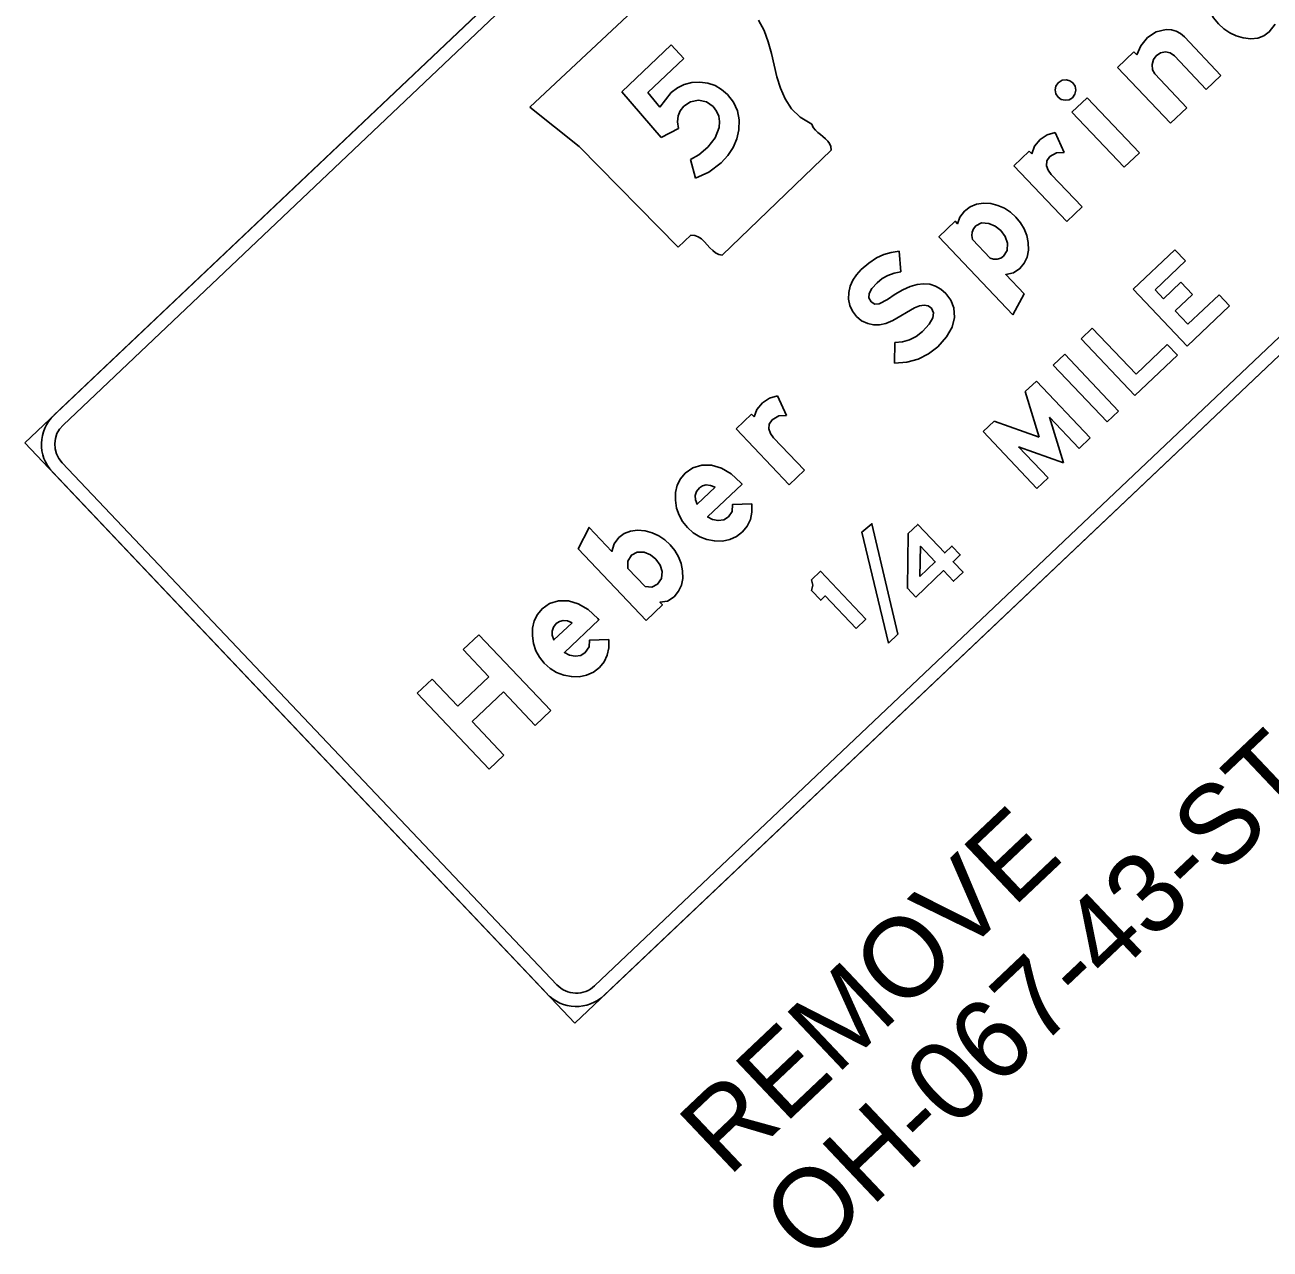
# Model space of a CAD drawing. Extents: x 1289840 to 1295361, y 220865 to 226414.
# Drawn here: x 1291418.9 to 1291512.4, y 222085.2 to 222177.1 of the extents above; entities that cross this region are included whole.
import ezdxf

# ---------------------------------------------------------------- set-up
doc = ezdxf.new("R2010")
doc.units = 0
doc.layers.add('P_TC_Signs_Permanent', color=7, linetype='Continuous')
doc.layers.add('R_OVHD_Sign', color=7, linetype='Continuous')

msp = doc.modelspace()

# ---------------------------------------------------------------- linework, layer by layer
at = {"layer": 'R_OVHD_Sign'}
for p, q in [((1291497.277, 222220.036), (1291418.89, 222145.744)), ((1291421.067, 222147.808), (1291495.1, 222217.973)), ((1291495.788, 222217.247), (1291421.755, 222147.082)), ((1291456.789, 222170.942), (1291468.823, 222182.203)), ((1291473.961, 222177.469), (1291474.386, 222176.683)), ((1291460.163, 222102.195), (1291538.551, 222176.488)), ((1291474.386, 222176.683), (1291474.695, 222175.844)), ((1291503.819, 222176.59), (1291503.173, 222176.157)), ((1291504.56, 222176.759), (1291503.819, 222176.59)), ((1291504.954, 222176.738), (1291504.56, 222176.759)), ((1291505.317, 222176.641), (1291504.954, 222176.738)), ((1291505.645, 222176.463), (1291505.317, 222176.641)), ((1291467.416, 222175.609), (1291463.706, 222172.093)), ((1291468.368, 222174.604), (1291467.416, 222175.609)), ((1291474.695, 222175.844), (1291474.929, 222174.976)), ((1291502.668, 222175.546), (1291502.358, 222174.861)), ((1291503.173, 222176.157), (1291502.668, 222175.546)), ((1291505.943, 222176.208), (1291505.645, 222176.463)), ((1291508.679, 222173.321), (1291505.943, 222176.208)), ((1291461.653, 222104.985), (1291535.685, 222175.15)), ((1291465.654, 222172.031), (1291468.368, 222174.604)), ((1291474.929, 222174.976), (1291475.133, 222174.084)), ((1291502.144, 222175.086), (1291500.917, 222173.922)), ((1291502.358, 222174.861), (1291502.144, 222175.086)), ((1291503.609, 222174.506), (1291503.817, 222174.796)), ((1291503.817, 222174.796), (1291504.149, 222175.022)), ((1291504.149, 222175.022), (1291504.509, 222175.101)), ((1291504.509, 222175.101), (1291504.864, 222175.023)), ((1291504.864, 222175.023), (1291505.185, 222174.785)), ((1291505.185, 222174.785), (1291507.569, 222172.269)), ((1291536.373, 222174.424), (1291462.341, 222104.259)), ((1291475.133, 222174.084), (1291475.343, 222173.209)), ((1291500.917, 222173.922), (1291504.89, 222169.73)), ((1291503.512, 222174.137), (1291503.609, 222174.506)), ((1291503.537, 222173.74), (1291503.512, 222174.137)), ((1291503.712, 222173.432), (1291503.537, 222173.74)), ((1291468.947, 222172.786), (1291468.389, 222172.645)), ((1291469.55, 222172.818), (1291468.947, 222172.786)), ((1291470.151, 222172.738), (1291469.55, 222172.818)), ((1291470.699, 222172.561), (1291470.151, 222172.738)), ((1291475.343, 222173.209), (1291475.602, 222172.358)), ((1291496.467, 222172.769), (1291496.286, 222172.517)), ((1291496.758, 222172.954), (1291496.467, 222172.769)), ((1291497.08, 222172.995), (1291496.758, 222172.954)), ((1291497.339, 222172.912), (1291497.08, 222172.995)), ((1291497.566, 222172.757), (1291497.339, 222172.912)), ((1291497.723, 222172.508), (1291497.566, 222172.757)), ((1291506.118, 222170.893), (1291503.712, 222173.432)), ((1291507.569, 222172.269), (1291508.679, 222173.321)), ((1291463.706, 222172.093), (1291466.657, 222168.656)), ((1291466.558, 222170.935), (1291465.654, 222172.031)), ((1291467.412, 222172.028), (1291466.558, 222170.935)), ((1291467.877, 222172.39), (1291467.412, 222172.028)), ((1291468.389, 222172.645), (1291467.877, 222172.39)), ((1291471.195, 222172.274), (1291470.699, 222172.561)), ((1291471.637, 222171.889), (1291471.195, 222172.274)), ((1291472.087, 222171.306), (1291471.637, 222171.889)), ((1291475.602, 222172.358), (1291475.957, 222171.558)), ((1291496.286, 222172.517), (1291496.228, 222172.234)), ((1291496.228, 222172.234), (1291496.286, 222171.948)), ((1291496.286, 222171.948), (1291496.452, 222171.701)), ((1291497.525, 222171.651), (1291497.71, 222171.906)), ((1291497.71, 222171.906), (1291497.774, 222172.209)), ((1291497.774, 222172.209), (1291497.723, 222172.508)), ((1291460.498, 222167.999), (1291456.789, 222170.942)), ((1291468.08, 222170.671), (1291468.345, 222171.005)), ((1291468.345, 222171.005), (1291468.862, 222171.342)), ((1291468.862, 222171.342), (1291469.464, 222171.454)), ((1291469.464, 222171.454), (1291470.056, 222171.333)), ((1291470.056, 222171.333), (1291470.548, 222170.983)), ((1291470.548, 222170.983), (1291470.814, 222170.632)), ((1291472.378, 222170.672), (1291472.087, 222171.306)), ((1291475.957, 222171.558), (1291476.444, 222170.826)), ((1291496.452, 222171.701), (1291496.692, 222171.524)), ((1291496.692, 222171.524), (1291496.981, 222171.453)), ((1291496.981, 222171.453), (1291497.272, 222171.491)), ((1291497.272, 222171.491), (1291497.525, 222171.651)), ((1291498.639, 222171.646), (1291497.491, 222170.559)), ((1291502.554, 222167.516), (1291498.639, 222171.646)), ((1291504.89, 222169.73), (1291506.118, 222170.893)), ((1291467.887, 222169.832), (1291467.927, 222170.281)), ((1291467.927, 222170.281), (1291468.08, 222170.671)), ((1291470.814, 222170.632), (1291470.979, 222170.256)), ((1291470.979, 222170.256), (1291471.045, 222169.853)), ((1291472.512, 222169.984), (1291472.378, 222170.672)), ((1291472.487, 222169.248), (1291472.512, 222169.984)), ((1291476.444, 222170.826), (1291477.098, 222170.185)), ((1291477.098, 222170.185), (1291477.97, 222169.658)), ((1291497.491, 222170.559), (1291501.406, 222166.428)), ((1291466.657, 222168.656), (1291467.955, 222169.331)), ((1291467.955, 222169.331), (1291467.887, 222169.832)), ((1291471.01, 222169.422), (1291470.717, 222168.647)), ((1291471.045, 222169.853), (1291471.01, 222169.422)), ((1291472.332, 222168.557), (1291472.487, 222169.248)), ((1291477.97, 222169.658), (1291478.077, 222169.424)), ((1291478.077, 222169.424), (1291478.231, 222169.224)), ((1291478.231, 222169.224), (1291478.407, 222169.049)), ((1291478.407, 222169.049), (1291478.604, 222168.885)), ((1291496.238, 222169.026), (1291495.626, 222168.865)), ((1291496.897, 222167.548), (1291496.238, 222169.026)), ((1291470.717, 222168.647), (1291470.15, 222167.947)), ((1291472.06, 222167.916), (1291472.332, 222168.557)), ((1291478.604, 222168.885), (1291478.801, 222168.726)), ((1291478.801, 222168.726), (1291478.991, 222168.569)), ((1291478.991, 222168.569), (1291479.164, 222168.398)), ((1291479.164, 222168.398), (1291479.294, 222168.206)), ((1291479.294, 222168.206), (1291479.384, 222167.986)), ((1291495.11, 222168.514), (1291494.693, 222168)), ((1291495.626, 222168.865), (1291495.11, 222168.514)), ((1291467.931, 222160.428), (1291460.498, 222167.999)), ((1291469.472, 222167.37), (1291468.868, 222167.007)), ((1291470.15, 222167.947), (1291469.472, 222167.37)), ((1291471.163, 222166.761), (1291471.669, 222167.315)), ((1291479.411, 222167.723), (1291471.234, 222159.833)), ((1291471.669, 222167.315), (1291472.06, 222167.916)), ((1291479.384, 222167.986), (1291479.411, 222167.723)), ((1291494.291, 222167.643), (1291493.136, 222166.548)), ((1291494.481, 222167.442), (1291494.291, 222167.643)), ((1291494.693, 222168), (1291494.481, 222167.442)), ((1291495.616, 222166.911), (1291495.834, 222167.23)), ((1291495.834, 222167.23), (1291496.323, 222167.521)), ((1291496.323, 222167.521), (1291496.897, 222167.548)), ((1291501.406, 222166.428), (1291502.554, 222167.516)), ((1291468.868, 222167.007), (1291469.242, 222165.62)), ((1291470.243, 222166.057), (1291471.163, 222166.761)), ((1291493.136, 222166.548), (1291497.109, 222162.356)), ((1291495.586, 222166.548), (1291495.616, 222166.911)), ((1291495.701, 222166.21), (1291495.586, 222166.548)), ((1291495.944, 222165.884), (1291495.701, 222166.21)), ((1291469.242, 222165.62), (1291470.243, 222166.057)), ((1291498.264, 222163.45), (1291495.944, 222165.884)), ((1291497.109, 222162.356), (1291498.264, 222163.45)), ((1291468.892, 222161.339), (1291467.931, 222160.428)), ((1291469.181, 222161.318), (1291468.892, 222161.339)), ((1291469.44, 222161.213), (1291469.181, 222161.318)), ((1291469.675, 222161.047), (1291469.44, 222161.213)), ((1291469.9, 222160.842), (1291469.675, 222161.047)), ((1291470.109, 222160.616), (1291469.9, 222160.842)), ((1291470.318, 222160.385), (1291470.109, 222160.616)), ((1291470.524, 222160.173), (1291470.318, 222160.385)), ((1291470.742, 222159.997), (1291470.524, 222160.173)), ((1291470.98, 222159.877), (1291470.742, 222159.997)), ((1291471.234, 222159.833), (1291470.98, 222159.877)), ((1291483.368, 222159.886), (1291482.813, 222159.619)), ((1291483.909, 222160.042), (1291483.368, 222159.886)), ((1291484.512, 222160.129), (1291483.909, 222160.042)), ((1291484.656, 222158.573), (1291484.512, 222160.129)), ((1291505.222, 222160.241), (1291502.095, 222157.277)), ((1291506.016, 222159.404), (1291505.222, 222160.241)), ((1291481.671, 222158.746), (1291481.317, 222158.357)), ((1291482.247, 222159.238), (1291481.671, 222158.746)), ((1291482.813, 222159.619), (1291482.247, 222159.238)), ((1291503.728, 222157.236), (1291506.016, 222159.404)), ((1291481.044, 222157.942), (1291480.853, 222157.5)), ((1291481.317, 222158.357), (1291481.044, 222157.942)), ((1291482.865, 222157.761), (1291483.249, 222158.069)), ((1291483.249, 222158.069), (1291483.678, 222158.309)), ((1291483.678, 222158.309), (1291484.146, 222158.475)), ((1291484.146, 222158.475), (1291484.656, 222158.573)), ((1291505.66, 222157.794), (1291504.364, 222156.565)), ((1291506.533, 222156.873), (1291505.66, 222157.794)), ((1291480.743, 222157.031), (1291480.724, 222156.525)), ((1291480.853, 222157.5), (1291480.743, 222157.031)), ((1291482.257, 222156.621), (1291482.279, 222156.954)), ((1291482.279, 222156.954), (1291482.481, 222157.334)), ((1291482.481, 222157.334), (1291482.865, 222157.761)), ((1291484.217, 222156.897), (1291483.643, 222156.493)), ((1291484.797, 222157.236), (1291484.217, 222156.897)), ((1291485.347, 222157.483), (1291484.797, 222157.236)), ((1291485.869, 222157.633), (1291485.347, 222157.483)), ((1291486.359, 222157.687), (1291485.869, 222157.633)), ((1291486.822, 222157.643), (1291486.359, 222157.687)), ((1291487.256, 222157.507), (1291486.822, 222157.643)), ((1291487.657, 222157.272), (1291487.256, 222157.507)), ((1291488.032, 222156.944), (1291487.657, 222157.272)), ((1291488.399, 222156.444), (1291488.032, 222156.944)), ((1291502.095, 222157.277), (1291506.143, 222153.006)), ((1291504.364, 222156.565), (1291503.728, 222157.236)), ((1291505.237, 222155.644), (1291506.533, 222156.873)), ((1291508.537, 222156.864), (1291506.189, 222154.639)), ((1291509.33, 222156.027), (1291508.537, 222156.864)), ((1291480.724, 222156.525), (1291480.813, 222156.057)), ((1291480.813, 222156.057), (1291481.012, 222155.624)), ((1291482.415, 222156.338), (1291482.257, 222156.621)), ((1291482.693, 222156.164), (1291482.415, 222156.338)), ((1291483.022, 222156.181), (1291482.693, 222156.164)), ((1291483.643, 222156.493), (1291483.022, 222156.181)), ((1291485.665, 222155.887), (1291486.057, 222156.039)), ((1291486.057, 222156.039), (1291486.401, 222156.084)), ((1291486.401, 222156.084), (1291486.694, 222156.017)), ((1291486.694, 222156.017), (1291486.94, 222155.841)), ((1291488.623, 222155.872), (1291488.399, 222156.444)), ((1291506.143, 222153.006), (1291509.33, 222156.027)), ((1291481.012, 222155.624), (1291481.319, 222155.227)), ((1291481.319, 222155.227), (1291481.699, 222154.913)), ((1291484.034, 222154.927), (1291485.665, 222155.887)), ((1291487.051, 222155.114), (1291486.774, 222154.643)), ((1291486.94, 222155.841), (1291487.107, 222155.511)), ((1291487.107, 222155.511), (1291487.051, 222155.114)), ((1291488.498, 222154.421), (1291488.68, 222155.147)), ((1291488.68, 222155.147), (1291488.623, 222155.872)), ((1291506.189, 222154.639), (1291505.237, 222155.644)), ((1291481.699, 222154.913), (1291482.162, 222154.694)), ((1291482.162, 222154.694), (1291482.589, 222154.597)), ((1291482.589, 222154.597), (1291483.043, 222154.604)), ((1291483.043, 222154.604), (1291483.524, 222154.713)), ((1291483.524, 222154.713), (1291484.034, 222154.927)), ((1291486.275, 222154.104), (1291485.806, 222153.728)), ((1291486.774, 222154.643), (1291486.275, 222154.104)), ((1291488.076, 222153.692), (1291488.498, 222154.421)), ((1291499.019, 222154.362), (1291498.176, 222153.562)), ((1291502.308, 222150.892), (1291499.019, 222154.362)), ((1291484.194, 222153.287), (1291484.16, 222151.712)), ((1291484.766, 222153.32), (1291484.194, 222153.287)), ((1291485.302, 222153.47), (1291484.766, 222153.32)), ((1291485.806, 222153.728), (1291485.302, 222153.47)), ((1291487.417, 222152.958), (1291488.076, 222153.692)), ((1291498.176, 222153.562), (1291502.223, 222149.291)), ((1291504.652, 222153.113), (1291502.308, 222150.892)), ((1291505.411, 222152.312), (1291504.652, 222153.113)), ((1291485.96, 222152.036), (1291486.73, 222152.421)), ((1291486.73, 222152.421), (1291487.417, 222152.958)), ((1291496.946, 222152.397), (1291496.085, 222151.581)), ((1291500.994, 222148.126), (1291496.946, 222152.397)), ((1291502.223, 222149.291), (1291505.411, 222152.312)), ((1291484.16, 222151.712), (1291485.103, 222151.797)), ((1291485.103, 222151.797), (1291485.96, 222152.036)), ((1291496.085, 222151.581), (1291500.133, 222147.31)), ((1291494.821, 222150.383), (1291493.981, 222149.587)), ((1291498.869, 222146.112), (1291494.821, 222150.383)), ((1291493.981, 222149.587), (1291495.029, 222146.177)), ((1291474.264, 222148.758), (1291473.848, 222148.244)), ((1291474.781, 222149.109), (1291474.264, 222148.758)), ((1291475.392, 222149.27), (1291474.781, 222149.109)), ((1291476.052, 222147.792), (1291475.392, 222149.27)), ((1291473.445, 222147.886), (1291472.291, 222146.792)), ((1291473.635, 222147.686), (1291473.445, 222147.886)), ((1291473.848, 222148.244), (1291473.635, 222147.686)), ((1291474.989, 222147.474), (1291475.478, 222147.765)), ((1291475.478, 222147.765), (1291476.052, 222147.792)), ((1291496.859, 222144.246), (1291495.808, 222147.659)), ((1291495.808, 222147.659), (1291498.029, 222145.316)), ((1291500.133, 222147.31), (1291500.994, 222148.126)), ((1291472.291, 222146.792), (1291476.264, 222142.599)), ((1291474.741, 222146.792), (1291474.771, 222147.155)), ((1291474.855, 222146.454), (1291474.741, 222146.792)), ((1291474.771, 222147.155), (1291474.989, 222147.474)), ((1291491.652, 222147.379), (1291490.816, 222146.587)), ((1291490.816, 222146.587), (1291494.864, 222142.316)), ((1291495.029, 222146.177), (1291491.652, 222147.379)), ((1291418.89, 222145.744), (1291460.163, 222102.195)), ((1291475.099, 222146.127), (1291474.855, 222146.454)), ((1291477.419, 222143.694), (1291475.099, 222146.127)), ((1291498.029, 222145.316), (1291498.869, 222146.112)), ((1291495.704, 222143.112), (1291493.483, 222145.456)), ((1291493.483, 222145.456), (1291496.859, 222144.246)), ((1291421.679, 222144.254), (1291458.825, 222105.061)), ((1291421.679, 222144.254), (1291421.679, 222144.254)), ((1291421.679, 222144.254), (1291421.679, 222144.254)), ((1291458.099, 222104.373), (1291420.953, 222143.567)), ((1291476.264, 222142.599), (1291477.419, 222143.694)), ((1291494.864, 222142.316), (1291495.704, 222143.112)), ((1291452.977, 222131.338), (1291451.799, 222130.222)), ((1291458.374, 222125.644), (1291452.977, 222131.338)), ((1291451.799, 222130.222), (1291453.724, 222128.191)), ((1291449.454, 222128), (1291448.338, 222126.942)), ((1291451.379, 222125.969), (1291449.454, 222128)), ((1291453.724, 222128.191), (1291451.379, 222125.969)), ((1291448.338, 222126.942), (1291453.735, 222121.247)), ((1291452.462, 222124.826), (1291454.807, 222127.048)), ((1291454.807, 222127.048), (1291457.196, 222124.527)), ((1291457.196, 222124.527), (1291458.374, 222125.644)), ((1291454.851, 222122.305), (1291452.462, 222124.826)), ((1291453.735, 222121.247), (1291454.851, 222122.305)), ((1291461.653, 222104.985), (1291461.653, 222104.985)), ((1291461.653, 222104.985), (1291461.653, 222104.985)), ((1291460.163, 222102.195), (1291460.163, 222102.195)), ((1291460.163, 222102.195), (1291460.163, 222102.195))]:
    msp.add_line(p, q, dxfattribs=at)
for points in [[(1291514.281, 222178.692), (1291510.338, 222182.852), (1291509.228, 222181.8), (1291509.403, 222181.615), (1291508.725, 222181.464), (1291508.199, 222181.132), (1291507.851, 222180.716), (1291507.625, 222180.253), (1291507.519, 222179.732), (1291507.531, 222179.164), (1291507.643, 222178.63), (1291507.841, 222178.13), (1291508.124, 222177.654), (1291508.496, 222177.206), (1291508.901, 222176.829), (1291509.344, 222176.531), (1291509.826, 222176.302), (1291510.343, 222176.147), (1291510.92, 222176.067), (1291511.438, 222176.113), (1291511.901, 222176.286), (1291512.307, 222176.585), (1291512.753, 222177.17)], [(1291493.065, 222155.343), (1291493.896, 222156.924), (1291492.525, 222158.371), (1291493.095, 222158.503), (1291493.582, 222158.828), (1291493.913, 222159.224), (1291494.128, 222159.682), (1291494.225, 222160.198), (1291494.205, 222160.775), (1291494.095, 222161.307), (1291493.904, 222161.805), (1291493.636, 222162.266), (1291493.291, 222162.693), (1291492.877, 222163.067), (1291492.426, 222163.361), (1291491.937, 222163.57), (1291491.41, 222163.703), (1291490.846, 222163.739), (1291490.329, 222163.655), (1291489.858, 222163.454), (1291489.434, 222163.135), (1291489.077, 222162.684), (1291488.907, 222162.189), (1291488.731, 222162.374), (1291487.504, 222161.21), (1291493.065, 222155.343)], [(1291491.357, 222159.603), (1291490.026, 222161.007), (1291489.971, 222161.297), (1291489.997, 222161.566), (1291490.103, 222161.811), (1291490.289, 222162.038), (1291490.711, 222162.256), (1291491.246, 222162.219), (1291491.729, 222162.015), (1291492.146, 222161.678), (1291492.476, 222161.226), (1291492.649, 222160.728), (1291492.632, 222160.191), (1291492.365, 222159.766), (1291492.151, 222159.616), (1291491.887, 222159.534), (1291491.609, 222159.526), (1291491.357, 222159.603)], [(1291473.466, 222141.172), (1291472.022, 222141.119), (1291471.98, 222140.602), (1291471.701, 222140.182), (1291471.357, 222139.968), (1291470.932, 222139.914), (1291470.514, 222139.985), (1291470.134, 222140.18), (1291472.728, 222142.639), (1291472.637, 222142.735), (1291471.905, 222143.406), (1291471.175, 222143.852), (1291470.439, 222144.069), (1291469.699, 222144.064), (1291469.022, 222143.855), (1291468.461, 222143.471), (1291468.103, 222143.045), (1291467.862, 222142.563), (1291467.736, 222142.025), (1291467.725, 222141.431), (1291467.814, 222140.852), (1291467.994, 222140.32), (1291468.262, 222139.827), (1291468.625, 222139.379), (1291469.066, 222138.983), (1291469.55, 222138.686), (1291470.079, 222138.483), (1291470.653, 222138.377), (1291471.251, 222138.368), (1291471.802, 222138.482), (1291472.305, 222138.715), (1291472.759, 222139.066), (1291473.114, 222139.492), (1291473.352, 222139.985), (1291473.469, 222140.542), (1291473.466, 222141.172)], [(1291470.711, 222142.422), (1291469.35, 222141.132), (1291469.223, 222141.476), (1291469.21, 222141.794), (1291469.309, 222142.088), (1291469.522, 222142.356), (1291469.766, 222142.521), (1291470.045, 222142.586), (1291470.359, 222142.552), (1291470.711, 222142.422)], [(1291465.522, 222132.419), (1291466.75, 222133.582), (1291466.565, 222133.777), (1291467.123, 222133.87), (1291467.62, 222134.196), (1291467.958, 222134.598), (1291468.179, 222135.055), (1291468.281, 222135.569), (1291468.266, 222136.141), (1291468.158, 222136.678), (1291467.967, 222137.184), (1291467.693, 222137.655), (1291467.332, 222138.098), (1291466.92, 222138.473), (1291466.468, 222138.773), (1291465.979, 222138.991), (1291465.449, 222139.134), (1291464.874, 222139.186), (1291464.355, 222139.121), (1291463.888, 222138.937), (1291463.476, 222138.633), (1291463.115, 222138.151), (1291462.952, 222137.59), (1291461.247, 222139.389), (1291460.436, 222137.785), (1291465.522, 222132.419)], [(1291483.717, 222130.719), (1291484.429, 222131.393), (1291482.475, 222139.676), (1291481.723, 222139.046), (1291483.717, 222130.719)], [(1291485.768, 222134.164), (1291487.861, 222136.149), (1291488.611, 222135.357), (1291489.316, 222136.026), (1291488.566, 222136.817), (1291489.106, 222137.328), (1291488.478, 222137.991), (1291487.939, 222137.479), (1291485.914, 222139.616), (1291485.209, 222138.948), (1291485.14, 222134.827), (1291485.768, 222134.164)], [(1291465.444, 222134.96), (1291464.162, 222136.312), (1291464.152, 222136.865), (1291464.425, 222137.314), (1291464.85, 222137.544), (1291465.38, 222137.53), (1291465.848, 222137.34), (1291466.257, 222137.009), (1291466.574, 222136.564), (1291466.721, 222136.084), (1291466.671, 222135.57), (1291466.386, 222135.144), (1291465.954, 222134.911), (1291465.444, 222134.96)], [(1291486.066, 222135.705), (1291486.127, 222137.979), (1291487.233, 222136.811), (1291486.066, 222135.705)], [(1291481.288, 222131.818), (1291482.019, 222132.511), (1291478.616, 222136.101), (1291477.938, 222135.458), (1291478.031, 222135.058), (1291477.943, 222134.657), (1291478.631, 222133.931), (1291478.976, 222134.258), (1291481.288, 222131.818)], [(1291462.724, 222130.991), (1291461.28, 222130.939), (1291461.238, 222130.421), (1291460.959, 222130.001), (1291460.615, 222129.788), (1291460.19, 222129.733), (1291459.772, 222129.804), (1291459.392, 222129.999), (1291461.986, 222132.458), (1291461.895, 222132.554), (1291461.163, 222133.225), (1291460.433, 222133.671), (1291459.697, 222133.888), (1291458.957, 222133.883), (1291458.28, 222133.674), (1291457.719, 222133.29), (1291457.361, 222132.865), (1291457.12, 222132.383), (1291456.994, 222131.844), (1291456.983, 222131.251), (1291457.072, 222130.671), (1291457.252, 222130.14), (1291457.52, 222129.646), (1291457.883, 222129.198), (1291458.324, 222128.802), (1291458.808, 222128.505), (1291459.337, 222128.302), (1291459.911, 222128.196), (1291460.509, 222128.187), (1291461.06, 222128.301), (1291461.563, 222128.534), (1291462.017, 222128.885), (1291462.372, 222129.311), (1291462.61, 222129.804), (1291462.727, 222130.362), (1291462.724, 222130.991)], [(1291459.969, 222132.241), (1291458.608, 222130.951), (1291458.481, 222131.295), (1291458.468, 222131.614), (1291458.567, 222131.907), (1291458.78, 222132.175), (1291459.024, 222132.341), (1291459.303, 222132.406), (1291459.617, 222132.372), (1291459.969, 222132.241)]]:
    msp.add_lwpolyline(points, dxfattribs=at)
for centre, radius, start, end in [((1291423.131, 222145.63), 3, 133.46382, 223.46346), ((1291423.131, 222145.63), 2, 133.46382, 223.46346), ((1291460.277, 222106.436), 2, 223.46346, 313.46367), ((1291460.277, 222106.436), 3, 223.46346, 313.46367)]:
    msp.add_arc(centre, radius, start, end, dxfattribs=at)

# ---------------------------------------------------------------- texts
at = {"layer": 'P_TC_Signs_Permanent'}
for s, p in [('OH-067-43-STA49+90NB-C', (1291477.893, 222084.034)), ('REMOVE', (1291471.705, 222090.569))]:
    msp.add_text(s, height=6, rotation=43.43866, dxfattribs=at).set_placement(p)

doc.saveas('drawing.dxf')
